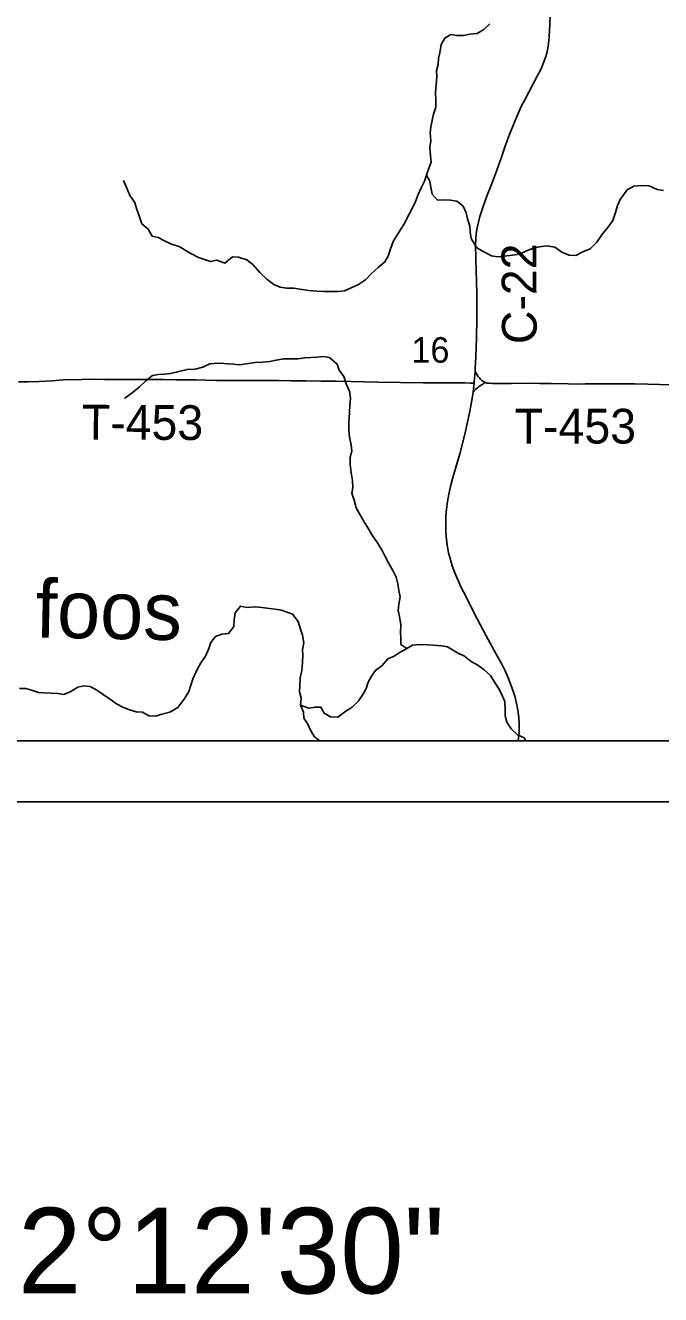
# Model space of a CAD drawing. Extents: x -7.5 to 53.5, y 0 to 22.
# Drawn here: x 6.558 to 7.597, y 13.194 to 15.27 of the extents above; entities that cross this region are included whole.
import ezdxf

# ---------------------------------------------------------------- set-up
doc = ezdxf.new("R2010")
doc.units = 0
for name, color, linetype in [('GM_X_Corporation', 7, 'Continuous'), ('GM_X_County_Road', 7, 'Continuous'), ('GM_X_County_Road_Text', 7, 'Continuous'), ('GM_X_Minor_River', 7, 'Continuous'), ('GM_X_Minor_River_Text', 7, 'Continuous'), ('GM_X_Section_Text', 7, 'Continuous'), ('GM_X_Township_Road', 7, 'Continuous'), ('GM_X_Township_Road_Text', 7, 'Continuous'), ('SH_Data', 7, 'Continuous'), ('SH_Text', 7, 'Continuous')]:
    doc.layers.add(name, color=color, linetype=linetype)

msp = doc.modelspace()

# ---------------------------------------------------------------- linework, layer by layer
at = {"layer": 'GM_X_Corporation'}
msp.add_lwpolyline([(4.6021, 15.6139), (4.6087, 14.5302), (4.6147, 14.1199), (4.6149, 14.11), (4.6151, 14.1), (8.9, 14.1), (8.9, 19.1887)], dxfattribs=at)
at = {"layer": 'GM_X_County_Road'}
for points in [[(7.2938, 14.7042), (7.2941, 14.7095), (7.2951, 14.7281), (7.2962, 14.7591), (7.2966, 14.7902), (7.2967, 14.8119), (7.2966, 14.8305), (7.2962, 14.8522), (7.2956, 14.8677), (7.295, 14.8895), (7.2948, 14.9112), (7.295, 14.9206), (7.2958, 14.9299), (7.2972, 14.9392), (7.2992, 14.9484), (7.3016, 14.9574), (7.3064, 14.9722), (7.3138, 14.9927), (7.3194, 15.0072), (7.3239, 15.0187), (7.3293, 15.0332), (7.3375, 15.0566), (7.3437, 15.0742), (7.3501, 15.0917), (7.3581, 15.112), (7.3643, 15.1263), (7.3695, 15.1376), (7.3751, 15.1487), (7.3956, 15.187), (7.4012, 15.1981), (7.4049, 15.2065), (7.4082, 15.2152), (7.41, 15.2211), (7.4115, 15.227), (7.4132, 15.2361), (7.4143, 15.2453), (7.4154, 15.2608), (7.4164, 15.2856)], [(7.2923, 14.6849), (7.2926, 14.6878), (7.2938, 14.7042)], [(7.2907, 14.6703), (7.2914, 14.6755), (7.2923, 14.6849)], [(7.3443, 14.2117), (7.3431, 14.2145), (7.3376, 14.2255), (7.3286, 14.2419), (7.312, 14.2717), (7.2974, 14.2992), (7.2848, 14.3242), (7.2793, 14.3353), (7.2708, 14.3519), (7.2655, 14.3631), (7.2607, 14.3747), (7.2565, 14.3864), (7.2529, 14.3984), (7.2506, 14.4074), (7.2488, 14.4166), (7.2471, 14.429), (7.2461, 14.4414), (7.2458, 14.4539), (7.2462, 14.4664), (7.2472, 14.4788), (7.2488, 14.4912), (7.251, 14.5035), (7.2536, 14.5157), (7.2576, 14.5307), (7.2689, 14.5695), (7.2744, 14.5905), (7.2787, 14.6087), (7.2821, 14.6238), (7.2852, 14.6389), (7.2887, 14.6571), (7.2902, 14.6662), (7.2907, 14.6703)], [(7.3643, 14.1), (7.3643, 14.1006), (7.3657, 14.1129), (7.366, 14.119), (7.3659, 14.1282), (7.3653, 14.1375), (7.3642, 14.1467), (7.3625, 14.1558), (7.3606, 14.1659), (7.3587, 14.1728), (7.3565, 14.1797), (7.3524, 14.1915), (7.3481, 14.2031), (7.3443, 14.2117)]]:
    msp.add_lwpolyline(points, dxfattribs=at)
at = {"layer": 'GM_X_Minor_River'}
for points in [[(7.3182, 15.2729), (7.3081, 15.2637), (7.2971, 15.2571), (7.2854, 15.2559), (7.2748, 15.2539), (7.2638, 15.2535), (7.2543, 15.2553), (7.2442, 15.2495), (7.2382, 15.2392), (7.236, 15.2255), (7.2342, 15.216), (7.2336, 15.2062), (7.231, 15.1959), (7.2311, 15.1864), (7.2301, 15.1731), (7.2294, 15.1606)], [(7.2294, 15.1606), (7.2299, 15.1473), (7.2297, 15.1363), (7.226, 15.1253), (7.2238, 15.1146), (7.2216, 15.1044), (7.2202, 15.0945), (7.2214, 15.0812), (7.22, 15.0706), (7.2209, 15.057), (7.2218, 15.0467), (7.2177, 15.0349), (7.2144, 15.025), (7.2111, 15.0155), (7.2055, 15.0045), (7.201, 14.9934), (7.1962, 14.9824), (7.1899, 14.9687), (7.1835, 14.9565), (7.1787, 14.9462), (7.1716, 14.9351), (7.16, 14.9165), (7.1549, 14.9031), (7.1523, 14.8936), (7.1463, 14.8833), (7.1362, 14.8745), (7.1238, 14.8638), (7.1144, 14.8539), (7.1031, 14.8466), (7.0925, 14.8415), (7.0801, 14.8361), (7.0702, 14.8349), (7.0464, 14.8347), (7.035, 14.8357), (7.0221, 14.8368), (7.0073, 14.8386), (6.9974, 14.8404), (6.9853, 14.8406), (6.975, 14.8421), (6.9648, 14.8465), (6.9533, 14.8552), (6.9419, 14.8661), (6.9304, 14.8789), (6.9205, 14.8868), (6.9072, 14.8912), (6.8969, 14.8919), (6.8845, 14.8815), (6.8716, 14.886), (6.8614, 14.884), (6.8515, 14.8873), (6.8416, 14.8903), (6.8279, 14.8974), (6.81, 14.9086), (6.7975, 14.9123), (6.7872, 14.9175), (6.7754, 14.9231), (6.7659, 14.9253), (6.7593, 14.937), (6.749, 14.9457), (6.7444, 14.9585), (6.7401, 14.9706), (6.7373, 14.9808), (6.7293, 14.9922), (6.7243, 15.0039), (6.7188, 15.0164)], [(7.2144, 15.025), (7.2201, 15.0152), (7.2214, 15.005), (7.2237, 14.9944), (7.2326, 14.9842), (7.2439, 14.9851), (7.2534, 14.9844), (7.264, 14.9826), (7.2743, 14.9747), (7.2793, 14.9637), (7.2813, 14.9539), (7.2852, 14.9418), (7.2861, 14.9319), (7.2873, 14.9217), (7.2969, 14.9066), (7.3095, 14.8995), (7.3205, 14.8935), (7.3308, 14.8917), (7.3414, 14.8929), (7.355, 14.8942), (7.3667, 14.8958), (7.3777, 14.9016), (7.3875, 14.9051), (7.3985, 14.9082), (7.4113, 14.9098), (7.4242, 14.9073), (7.4357, 14.8994), (7.4475, 14.8946), (7.4588, 14.8939), (7.4701, 14.8997), (7.4822, 14.9047), (7.4931, 14.9155), (7.5025, 14.9292), (7.5111, 14.9395), (7.5189, 14.9513), (7.5237, 14.9643), (7.5267, 14.9757), (7.5311, 14.9852), (7.5427, 15.0012), (7.5537, 15.0074), (7.5665, 15.0083), (7.5787, 15.0076), (7.5916, 15.002), (7.6018, 15.0002)], [(7.182, 14.2508), (7.1725, 14.2572), (7.1724, 14.2671), (7.1719, 14.2773), (7.1725, 14.2898), (7.1702, 14.3031), (7.1682, 14.3129), (7.1692, 14.3236), (7.1714, 14.3357), (7.1694, 14.346), (7.1674, 14.3569), (7.165, 14.3675), (7.1592, 14.3785), (7.1523, 14.391), (7.1469, 14.4015), (7.1415, 14.4121), (7.1342, 14.4238), (7.1258, 14.4363), (7.1184, 14.4483), (7.1127, 14.4582), (7.105, 14.4714), (7.0992, 14.4812), (7.0964, 14.4933), (7.0925, 14.505), (7.094, 14.5145), (7.0935, 14.5259), (7.0911, 14.5388), (7.0898, 14.5521), (7.0897, 14.5638), (7.0923, 14.5737), (7.0914, 14.5839), (7.0883, 14.5964), (7.0874, 14.6082), (7.0873, 14.6211), (7.0883, 14.637), (7.089, 14.6488), (7.0904, 14.6602), (7.0884, 14.6719), (7.0833, 14.684), (7.0791, 14.6957), (7.0718, 14.7063), (7.0683, 14.7161), (7.056, 14.727), (7.0466, 14.7285), (7.0356, 14.7276), (7.0155, 14.7263), (7.0042, 14.7247), (6.9939, 14.725), (6.981, 14.7249), (6.9686, 14.7225), (6.958, 14.7205), (6.9462, 14.7193), (6.9345, 14.7188), (6.9197, 14.7164), (6.908, 14.7148), (6.8985, 14.7162), (6.883, 14.7173), (6.8735, 14.7176), (6.8602, 14.7167), (6.8489, 14.7113), (6.8361, 14.7081), (6.8228, 14.7076), (6.8073, 14.7033), (6.796, 14.7006), (6.7858, 14.6998), (6.7759, 14.6989), (6.7661, 14.6977), (6.7559, 14.6893), (6.7443, 14.6785), (6.733, 14.669), (6.7232, 14.662), (6.7206, 14.6598)], [(6.5491, 14.1852), (6.5593, 14.1853), (6.5699, 14.1824), (6.5798, 14.1787), (6.5893, 14.1784), (6.6003, 14.1781), (6.6113, 14.1774), (6.6215, 14.1756), (6.6328, 14.1806), (6.6441, 14.1879), (6.6543, 14.1899), (6.6642, 14.1885), (6.6753, 14.1825), (6.6859, 14.1758), (6.6974, 14.1675), (6.7073, 14.1604), (6.7176, 14.1548), (6.7271, 14.1511), (6.7396, 14.1474), (6.7498, 14.1467), (6.7605, 14.1407), (6.7719, 14.1401), (6.7817, 14.1436), (6.7946, 14.1467), (6.8078, 14.1544), (6.8182, 14.1678), (6.8257, 14.1803), (6.8298, 14.1925), (6.8327, 14.2024), (6.8386, 14.2157), (6.8454, 14.2272), (6.8528, 14.2382), (6.8584, 14.2508), (6.8617, 14.2607), (6.8696, 14.2706), (6.8798, 14.2745), (6.8908, 14.2757), (6.8994, 14.2868), (6.8997, 14.2978), (6.9018, 14.3092), (6.9101, 14.3199), (6.9207, 14.3181), (6.934, 14.319), (6.9453, 14.3179), (6.9575, 14.3161), (6.9669, 14.3154), (6.9772, 14.3136), (6.9954, 14.3073), (7.0046, 14.2949), (7.0085, 14.2828), (7.0117, 14.2729), (7.0137, 14.2601), (7.0115, 14.249), (7.012, 14.2392), (7.0117, 14.2278), (7.0103, 14.2149), (7.0078, 14.2027), (7.0075, 14.1902), (7.0068, 14.18), (7.0096, 14.1694), (7.0085, 14.158), (7.0132, 14.147), (7.014, 14.1371), (7.0206, 14.1273), (7.0248, 14.1171), (7.0314, 14.1066), (7.0399, 14.1)], [(7.0085, 14.158), (7.0218, 14.1531), (7.0321, 14.1551), (7.0415, 14.1548), (7.0469, 14.145), (7.0572, 14.139), (7.0693, 14.1384), (7.0825, 14.1483), (7.0927, 14.1549), (7.1036, 14.1656), (7.1103, 14.1759), (7.1155, 14.1854), (7.1192, 14.1961), (7.1244, 14.2056), (7.1308, 14.2151), (7.1417, 14.2232), (7.1511, 14.2339), (7.1613, 14.2385), (7.1714, 14.2447), (7.182, 14.2508), (7.1918, 14.2562), (7.2024, 14.2575), (7.216, 14.2568), (7.2255, 14.2561), (7.2396, 14.2551), (7.249, 14.2537), (7.265, 14.2436), (7.2765, 14.2384), (7.2875, 14.2297), (7.2982, 14.2237), (7.3089, 14.2162), (7.3192, 14.2065), (7.3269, 14.1944), (7.3334, 14.1842), (7.338, 14.174), (7.3423, 14.1642), (7.3432, 14.1505), (7.3433, 14.141), (7.346, 14.1304), (7.3533, 14.1191), (7.3633, 14.1097), (7.3739, 14.1045), (7.3767, 14.1)]]:
    msp.add_lwpolyline(points, dxfattribs=at)
at = {"layer": 'GM_X_Township_Road'}
for points in [[(7.2923, 14.6849), (7.2926, 14.6878), (7.2938, 14.7042)], [(7.2938, 14.7042), (7.2971, 14.6988), (7.2991, 14.6959), (7.3007, 14.694), (7.3029, 14.6915), (7.305, 14.6895), (7.3075, 14.6877), (7.3102, 14.6863), (7.311, 14.686)], [(6.5472, 14.687), (6.5626, 14.6872), (6.5811, 14.6878), (6.6027, 14.6886), (6.6204, 14.6902), (6.65, 14.6912), (6.67, 14.6914), (6.6881, 14.691), (6.7036, 14.6907), (6.722, 14.6909), (6.7413, 14.691), (6.7607, 14.6909), (6.7836, 14.6907), (6.8048, 14.6905), (6.8371, 14.6902), (6.8712, 14.6895), (6.8898, 14.6894), (6.9053, 14.6895), (6.9239, 14.6895), (6.9363, 14.6895), (6.9508, 14.6893), (6.9732, 14.6891), (6.9929, 14.6889), (7.0173, 14.6886), (7.0424, 14.6884), (7.0663, 14.6881), (7.0912, 14.6877), (7.1346, 14.6867), (7.2091, 14.6857), (7.2308, 14.6856), (7.2463, 14.6856), (7.2648, 14.6857), (7.2771, 14.6855), (7.2862, 14.6851), (7.2923, 14.6849)], [(7.2907, 14.6703), (7.2952, 14.675), (7.2977, 14.6774), (7.2994, 14.6789), (7.3012, 14.6803), (7.3037, 14.6819), (7.3069, 14.6837), (7.311, 14.686)], [(7.311, 14.686), (7.3134, 14.6852), (7.3172, 14.6848), (7.3223, 14.6846), (7.3346, 14.6844), (7.3532, 14.6845), (7.3812, 14.6848), (7.3998, 14.6846), (7.4183, 14.6842), (7.4461, 14.6837), (7.4615, 14.6836), (7.4739, 14.6838), (7.5143, 14.684), (7.5268, 14.6839), (7.5548, 14.6838), (7.5765, 14.6834), (7.5952, 14.6829), (7.6138, 14.6823)]]:
    msp.add_lwpolyline(points, dxfattribs=at)
at = {"layer": 'SH_Data'}
for p, q in [((2.1, 14.1), (8.9, 14.1)), ((2, 14), (9, 14))]:
    msp.add_line(p, q, dxfattribs=at)

# ---------------------------------------------------------------- texts
at = {"layer": 'GM_X_County_Road_Text'}
msp.add_text('C-22', height=0.05682, rotation=90.3213, dxfattribs=at).set_placement((7.3948, 14.749))
at = {"layer": 'GM_X_Minor_River_Text'}
msp.add_text('foos', height=0.09471, rotation=358.8693, dxfattribs=at).set_placement((6.5744, 14.2691))
at = {"layer": 'GM_X_Section_Text'}
msp.add_text('16', height=0.04186, rotation=0, dxfattribs=at).set_placement((7.1897, 14.7184))
at = {"layer": 'GM_X_Township_Road_Text'}
for rotation, p in [(359.7241, (6.6506, 14.5929)), (0, (7.3586, 14.5862))]:
    msp.add_text('T-453', height=0.05682, rotation=rotation, dxfattribs=at).set_placement(p)
at = {"layer": 'SH_Text'}
msp.add_text('LATITUDE:  40°38\'40"     LONGITUDE:  82°12\'30"', height=0.14, dxfattribs=at).set_placement((3.071, 13.1959))

doc.saveas('drawing.dxf')
